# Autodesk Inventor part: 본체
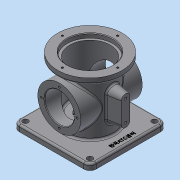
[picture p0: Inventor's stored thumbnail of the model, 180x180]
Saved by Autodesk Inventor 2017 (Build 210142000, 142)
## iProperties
Created: 2017-08
Part Number: 본체
Material: 알루미늄 6061
Document SubType Name: Modeling
Designer: mduedu
Density: 2.71 g/cm^3
Mass: 951.115 g
Surface Area: 966.539 cm^2
Volume: 350.965 cm^3
Appearance: 기본값
Author: mduedu
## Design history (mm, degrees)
sketch "스케치1"
  geometry: L1 (-62.5, -62.5)-(62.5, -62.5); L2 (62.5, -62.5)-(62.5, 62.5); L3 (62.5, 62.5)-(-62.5, 62.5); L4 (-62.5, 62.5)-(-62.5, -62.5); L5 (-62.5, -62.5)-(62.5, 62.5); L6 (62.5, -62.5)-(-62.5, 62.5); 1 further point
  constraints: 12 end point, 2 midpoint, 2 parallel, 1 horizontal, 1 perpendicular
  dimensions: "d232" = 125 distance of L3.end L2.end; "d233" = 125 distance of L2.end L1.end
extrude "돌출1" new body sketch "스케치1" distance "d5" = 10; taper "d6" = 0 deg
sketch "스케치2"
  geometry: C1 r 38 at (0, 0); 1 further point
  constraints: 1 centre point, 1 coincident
  dimensions: "d111" = 76 diameter of C1
extrude "돌출2" join sketch "스케치2" distance "d12" = 88; taper "d13" = 0 deg
sketch "스케치3"
  geometry: C1 r 52.5 at (0, 0); 1 further point
  constraints: 1 centre point, 1 coincident
  dimensions: "d114" = 105 diameter of C1
extrude "돌출3" join sketch "스케치3" distance "d19" = 10; taper "d20" = 0 deg
sketch "스케치4"
  geometry: C1 r 33 at (0, 0); 1 further point
  constraints: 1 centre point, 1 coincident
  dimensions: "d115" = 66 diameter of C1
extrude "돌출4" cut sketch "스케치4" distance "d26" = 86; taper "d27" = 0 deg
sketch "스케치5"
  geometry: C1 r 37 at (0, 0); 1 further point
  constraints: 1 centre point, 1 coincident
  dimensions: "d116" = 74 diameter of C1
extrude "돌출5" cut sketch "스케치5" distance "d29" = 7; taper "d30" = 0 deg
node "작업 평면1"
sketch "스케치18"
  geometry: L1 (-62.5, 0)-(62.5, 0) reference; C1 r 35 at (0, 54); 1 further point
  constraints: 1 centre point, 1 vertical alignment
  dimensions: "d118" = 70 diameter of C1; "d234" = 54 distance from line of C1.centre L1
extrude "돌출9" join sketch "스케치18" stored distance "d120" = 10; taper "d121" = 0 deg
hole "구멍8" diameter "d124" = 48; stored, may be unused: countersink angle "d128" = 90 deg, drill point angle "d130" = 118 deg; dims "d122" = 10, "d123" = 10, "d125" = 6, "d126" = 4, "d127" = 2, "d129" = 8
sketch "스케치9"
  geometry: C1 r 33 at (0, 0); 1 further point
  constraints: 1 centre point, 1 coincident
  dimensions: "d131" = 66 diameter of C1
extrude "돌출8" cut sketch "스케치9" distance "d43" = 16; taper "d44" = 0 deg
node "작업 평면2"
fillet "모깎기9" dims "d137" = 3
fillet "모깎기10" dims "d138" = 3
chamfer "모따기2" distance "d139" = 1; stored, may be unused: second distance "d140" = 2, angle "d141" = 45 deg
fillet "모깎기11" dims "d142" = 3
fillet "모깎기12" dims "d143" = 3
fillet "모깎기13" dims "d144" = 3
node "작업 평면3"
sketch "스케치20"
  geometry: L1 (108, -52.5)-(108, 52.5) reference; L2 (37, 7)-(71, 7); L3 (37, -7)-(71, -7); L4 (0, -33)-(0, 33) reference; A1 r 7 centre (37, 0) between (37, 7) and (37, -7); A2 r 7 centre (71, 0) between (71, 7) and (71, -7); 1 further point
  constraints: 4 end point, 4 point on circle, 3 tangent, 2 centre point, 2 horizontal alignment, 1 parallel, 1 perpendicular
  dimensions: "d203" = 14 diameter of A1; "d206" = 30 distance edge to line of A2 L1; "d207" = 48 dimension on A2 A1 (derived); "d236" = 30 distance edge to line of A1 L4
extrude "돌출10" join sketch "스케치20" stored distance "d152" = 10; taper "d153" = 10 deg
sketch "스케치21"
  geometry: C1 r 7 at (0, 71) reference; C2 r 7 at (0, 37) reference; 3 further points
  constraints: 2 coincident
hole "구멍12" sketch "스케치21" at (0, 71), (0, 37) diameter "d219" = 4.134; stored, may be unused: countersink angle "d223" = 90 deg, drill point angle "d225" = 118 deg; dims "d220" = 6, "d221" = 4, "d222" = 2, "d224" = 8
fillet "모깎기18" dims "d229" = 3
sketch "스케치23"
  geometry: C1 r 20 at (0, 0); 1 further point
  constraints: 1 centre point, 1 coincident
  dimensions: "d168" = 40 diameter of C1
extrude "돌출12" cut sketch "스케치23" stored distance "d169" = 148.25; taper "d170" = 0 deg
sketch "스케치28"
  geometry: L1 (62.5, -62.5)-(62.5, 62.5) reference; 2 further points
  constraints: 1 horizontal alignment, 1 other
  dimensions: "d238" = 10 distance from line of point (52.5, 0) L1
feature "엠보싱4" sketch "스케치28" dims "d239" = 0.5, "d240" = 0
sketch "스케치25" dims "d178" = 58
  geometry: C1 r 35 at (0, 0) reference; 3 further points
  constraints: 2 vertical alignment, 1 coincident, 2 other
hole "구멍10" sketch "스케치25" at (0, 29) diameter "d179" = 3.242; stored, may be unused: countersink angle "d183" = 90 deg, drill point angle "d185" = 118 deg; dims "d180" = 4, "d181" = 4, "d182" = 2, "d184" = 6
sketch "스케치26" dims "d189" = 90
  geometry: 3 further points
  constraints: 2 vertical alignment, 1 coincident, 2 other
hole "구멍11" sketch "스케치26" at (0, 45) diameter "d190" = 3.242; stored, may be unused: countersink angle "d194" = 90 deg, drill point angle "d196" = 118 deg; dims "d191" = 4, "d192" = 4, "d193" = 2, "d195" = 6
chamfer "모따기4" distance "d200" = 1; stored, may be unused: second distance "d201" = 2, angle "d202" = 45 deg
fillet "모깎기19" dims "d241" = 10
sketch "스케치29"
  geometry: A1 r 10 centre (-52.5, 52.5) between (-52.5, 62.5) and (-62.5, 52.5) reference; A2 r 10 centre (52.5, 52.5) between (62.5, 52.5) and (52.5, 62.5) reference; A3 r 10 centre (52.5, -52.5) between (52.5, -62.5) and (62.5, -52.5) reference; A4 r 10 centre (-52.5, -52.5) between (-62.5, -52.5) and (-52.5, -62.5) reference; 5 further points
  constraints: 4 coincident
hole "구멍13" sketch "스케치29" at (-52.5, 52.5), (52.5, 52.5), (52.5, -52.5), (-52.5, -52.5) diameter "d242" = 9; stored, may be unused: countersink angle "d246" = 90 deg, drill point angle "d248" = 118 deg; dims "d243" = 6, "d244" = 4, "d245" = 2, "d247" = 8
fillet "모깎기20" dims "d249" = 3
node "솔리드1"
mirror "대칭2"
pattern_circular "원형 패턴1" dims angle "d187" = 360 deg
mirror "대칭3"
pattern_circular "원형 패턴2" dims angle "d198" = 360 deg
other parameters: "d147" = 58
